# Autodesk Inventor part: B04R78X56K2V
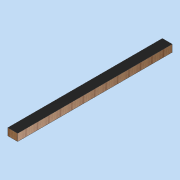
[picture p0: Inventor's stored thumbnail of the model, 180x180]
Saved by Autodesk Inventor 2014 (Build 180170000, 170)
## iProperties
Created: 2011-08
Part Number: B04R78X56K2V
Document SubType Name: Modeling
Designer: david.appleford
Density: 0.469135 g/cm^3
Description: Roof Edge Beam 1w - 2 Locks
Mass: 2500 g
Surface Area: 3356.96 cm^2
Volume: 5328.96 cm^3
Cost Center: £16.00
Material: 000 Redwood
Appearance: Wood (Oak)
Justset: False
Title: Roof Edge Beam 1w - 2 Locks
Author: david.appleford
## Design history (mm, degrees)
sketch "Sketch1"
  geometry: L1 (39, -34)-(-39, -34); L2 (-39, -34)-(-39, 1186); L3 (-39, 1186)-(39, 1186); L4 (39, 1186)-(39, -34); 1 further point
  constraints: 8 end point, 2 parallel, 1 horizontal, 1 perpendicular, 1 other
  dimensions: "d2" = 78 distance between parallel lines of L2 L4; "d3" = 34 distance from line of point (0, 0) L1; "d4" = 39 distance from line of point (0, 0) L2 (= 0.5 x d2); "d5" = 1220 distance of L3.end L1.start
extrude "Extrusion1" new body sketch "Sketch1" distance "d0" = 56; taper "d1" = 0 deg
body "Solid1"
